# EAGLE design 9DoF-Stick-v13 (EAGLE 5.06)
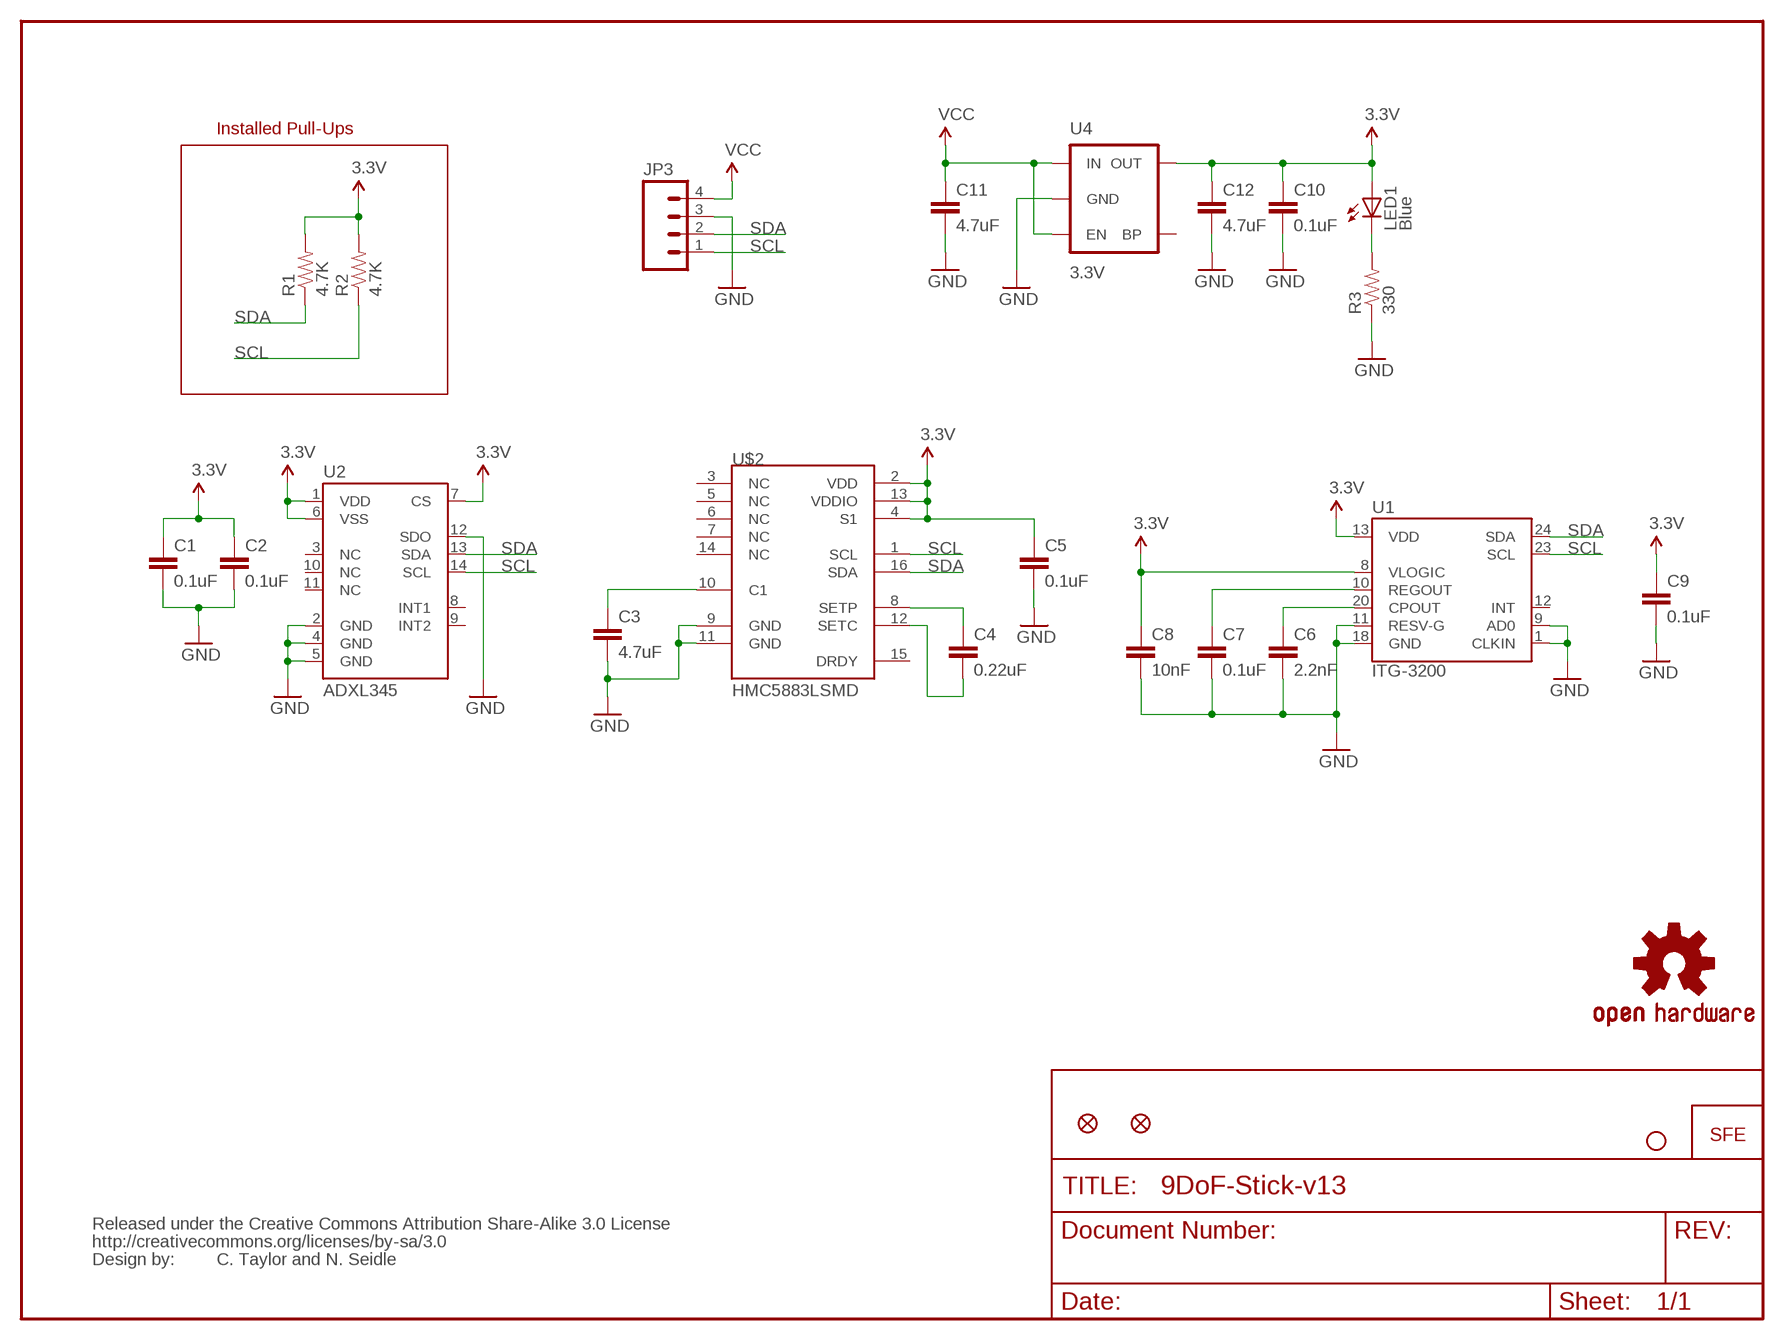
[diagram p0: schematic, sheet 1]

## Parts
C1  0.1uF  CAP0402-CAP  [0402-CAP]
C2  0.1uF  CAP0402-CAP  [0402-CAP]
C3  4.7uF  CAP0402-CAP  [0402-CAP]
C4  0.22uF  CAP0402-CAP  [0402-CAP]
C5  0.1uF  CAP0402-CAP  [0402-CAP]
C6  2.2nF  CAP0402-CAP  [0402-CAP]
C7  0.1uF  CAP0402-CAP  [0402-CAP]
C8  10nF  CAP0402-CAP  [0402-CAP]
C9  0.1uF  CAP0402-CAP  [0402-CAP]
C10  0.1uF  CAP0402-CAP  [0402-CAP]
C11  4.7uF  CAP0402-CAP  [0402-CAP]
C12  4.7uF  CAP0402-CAP  [0402-CAP]
JP1  FIDUCIAL1X2  [FIDUCIAL-1X2]
JP2  FIDUCIAL1X2  [FIDUCIAL-1X2]
JP3  M04PTH  [1X04]
JP4  LOGO-SFESK  [SFE-LOGO-FLAME]
JP5  STAND-OFF  [STAND-OFF]
LED1  Blue  LED0603  [LED-0603]
R1  4.7K  RESISTOR0402-RES  [0402-RES]
R2  4.7K  RESISTOR0402-RES  [0402-RES]
R3  330  RESISTOR0402-RES  [0402-RES]
U1  ITG-3200  [QFN-24]
U2  ADXL345  [LGA14]
U4  3.3V  V_REG_LDOSMD  [SOT23-5]
U$1  CREATIVE_COMMONS  [CREATIVE_COMMONS]
U$2  HMC5883LSMD  [16LPCC]
U$3  OSHW-LOGOS  [OSHW-LOGO-S]

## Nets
3.3V: C1.1 C2.1 C5.1 C8.1 C9.1 C10.1 C12.1 LED1.A R1.2 R2.2 U1.8(VLOGIC) U1.13(VDD) U2.1(VDD) U2.6(VSS) U2.7(CS) U4.5(OUT) U$2.2(VDD) U$2.4(S1) U$2.13(VDDIO)
GND: C1.2 C2.2 C3.2 C5.2 C6.2 C7.2 C8.2 C9.2 C10.2 C11.2 C12.2 JP3.3 R3.1 U1.1(CLKIN) U1.9(AD0) U1.11(RESV-G) U1.18(GND) U2.2(GND) U2.4(GND) U2.5(GND) U2.12(SDO) U4.2(GND) U$2.9(GND) U$2.11(GND)
N$1: C3.1 U$2.10(C1)
N$2: C4.1 U$2.8(SETP)
N$3: C4.2 U$2.12(SETC)
N$4: LED1.C R3.2
N$5: C6.1 U1.20(CPOUT)
N$7: C7.1 U1.10(REGOUT)
SCL: JP3.1 R2.1 U1.23(SCL) U2.14(SCL) U$2.1(SCL)
SDA: JP3.2 R1.1 U1.24(SDA) U2.13(SDA) U$2.16(SDA)
VCC: C11.1 JP3.4 U4.1(IN) U4.3(EN)
Unconnected: U1.12(INT) U2.3(NC) U2.8(INT1) U2.9(INT2) U2.10(NC) U2.11(NC) U4.4(BP) U$2.3(NC) U$2.5(NC) U$2.6(NC) U$2.7(NC) U$2.14(NC) U$2.15(DRDY)

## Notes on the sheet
- Installed Pull-Ups
- C. Taylor and N. Seidle

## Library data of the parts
C1-C12 = SparkFun:CAP: Capacitor
JP1 JP2 = SparkFun:FIDUCIAL: Fiducial Alignment Points
JP3 = SparkFun:M04: Header 4 Standard 4-pin 0.1" header. Use with straight break away headers (SKU : PRT-00116), right angle break away headers (PRT-00553), swiss pins (PRT-00743), machine pins (PRT-00117), and female headers (PRT-00115). Molex polarized connector foot print use with SKU : PRT-08231 with associated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
JP4 = SparkFun:LOGO-SFE: Spark Fun Electronics PCB Logo
JP5 = SparkFun:STAND-OFF: Stand Off
LED1 = SparkFun:LED: LEDs
R1-R3 = SparkFun:RESISTOR: Resistor
U1 = SparkFun:ITG-3200: ITG-3200 3-axis gyro, digital output, qfn24 package
U2 = SparkFun:ADXL345
U4 = SparkFun:V_REG_LDO: Voltage Regulator LDO Standard 150mA LDO voltage regulator in SOT-23 layout. Micrel part MIC5205. BP (by-pass) pin is used to lower output noise with 470pF cap.
U$1 = SparkFun:CREATIVE_COMMONS
U$2 = SparkFun:HMC5883L: 3 Axis Digital Compass IC
U$3 = SparkFun:OSHW-LOGO: Open Source Hardware Logo This logo indicates the piece of hardware it is found on incorporates a OSHW license and/or adheres to the definition of open source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

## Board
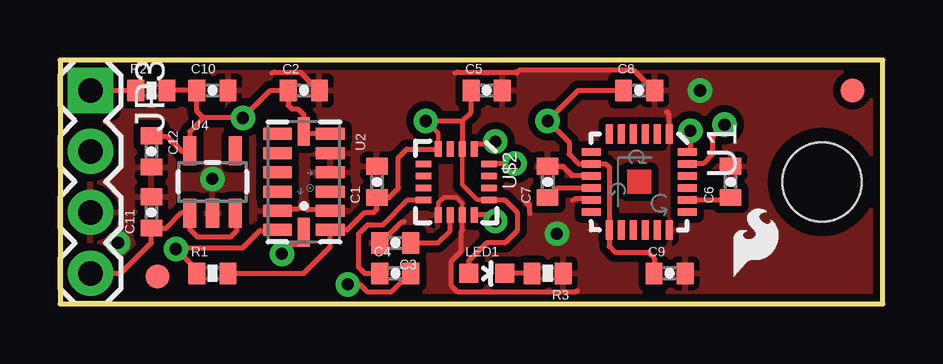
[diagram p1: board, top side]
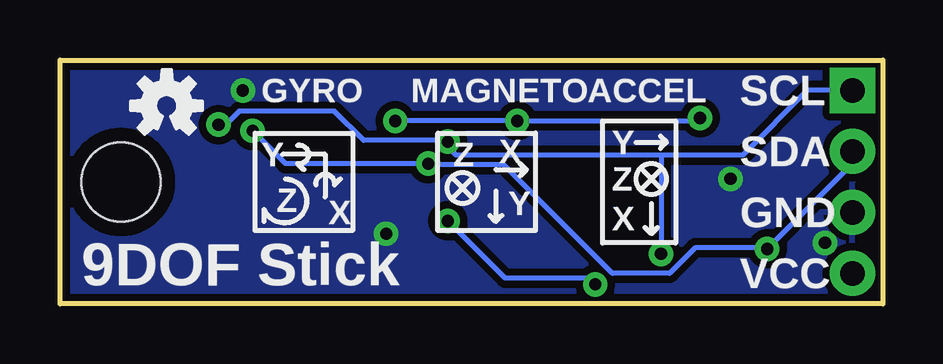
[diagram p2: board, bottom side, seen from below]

Size 34.29 x 10.16 mm. Coordinates in mm from the lower left corner, seen from the top.
Outline: 0,0 34.29,0 34.29,10.16 0,10.16 0,0
Copper layers (1*16): Top 0.035mm / dielectric 1.5mm / Bottom 0.035mm
Design rules "SparkFun *": minimum track width 7mil, minimum drill 20mil, track to track 8mil, track to pad 8mil, pad to pad 7mil, via to via 8mil, smd to smd 8mil, copper to edge 8mil, drill to drill 8mil, minimum pad ring 12mil, minimum via ring 10mil, stop-mask expansion 4mil, vias tented up to drill 20mil, thermal gap 10mil

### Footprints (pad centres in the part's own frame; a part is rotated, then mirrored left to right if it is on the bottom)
0402-CAP = smd 0.7 x 0.9: 1 -0.65,0; 2 0.65,0
FIDUCIAL-1X2 = smd 1 x 1: 1 0,0
1X04 = drill 1.016 pad 1.88 square: 1 0,0 | drill 1.016 pad 1.88 round: 2 2.54,0; 3 5.08,0; 4 7.62,0
STAND-OFF = hole 3.302: 0,0
LED-0603 = smd 0.8 x 0.8: A 0,-0.75; C 0,0.75
0402-RES = smd 0.7 x 0.9: 1 -0.65,0; 2 0.65,0
QFN-24 = smd 0.8 x 0.3: 1 -2,1.25; 2 -2,0.75; 3 -2,0.25; 4 -2,-0.25; 5 -2,-0.75; 6 -2,-1.25; 13 2,-1.25; 14 2,-0.75; 15 2,-0.25; 16 2,0.25; 17 2,0.75; 18 2,1.25 | smd 0.3 x 0.8: 7 -1.25,-2; 8 -0.75,-2; 9 -0.25,-2; 10 0.25,-2; 11 0.75,-2; 12 1.25,-2; 19 1.25,2; 20 0.75,2; 21 0.25,2; 22 -0.25,2; 23 -0.75,2; 24 -1.25,2
LGA14 = smd 0.5 x 1.2: 1 2,1.1; 2 1.2,1.1; 3 0.4,1.1; 4 -0.4,1.1; 5 -1.2,1.1; 6 -2,1.1; 8 -2,-1.1; 9 -1.2,-1.1; 10 -0.4,-1.1; 11 0.4,-1.1; 12 1.2,-1.1; 13 2,-1.1 | smd 1.2 x 0.5: 7 -2.1,0; 14 2.1,0
SOT23-5 = smd 0.55 x 1.2: 1 -0.95,-1.3; 2 0,-1.3; 3 0.95,-1.3; 4 0.95,1.3; 5 -0.95,1.3
16LPCC = smd 0.65 x 0.28: 1 -1.37,0.75; 2 -1.37,0.25; 3 -1.37,-0.25; 4 -1.37,-0.75; 9 1.37,-0.75; 10 1.37,-0.25; 11 1.37,0.25; 12 1.37,0.75 | smd 0.28 x 0.65: 5 -0.75,-1.37; 6 -0.25,-1.37; 7 0.25,-1.37; 8 0.75,-1.37; 13 0.75,1.37; 14 0.25,1.37; 15 -0.25,1.37; 16 -0.75,1.37

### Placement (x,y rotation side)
C1  13.21,5.08 90 top
C2  10.16,8.89 0 top
C3  13.97,2.54 180 top
C4  13.97,1.27 0 top
C5  17.78,8.89 0 top
C6  27.94,5.08 90 top
C7  20.32,5.08 90 top
C8  24.13,8.89 0 top
C9  25.4,1.27 0 top
C10  6.35,8.89 0 top
C11  3.81,3.81 90 top
C12  3.81,6.35 270 top
JP1  33.02,8.89 0 top
JP2  4.06,1.14 0 top
JP3  1.27,8.89 270 top
JP4  28.07,1.14 0 top
JP5  31.75,5.08 0 top
LED1  17.78,1.27 270 top
R1  6.35,1.27 0 top
R2  3.81,8.89 0 top
R3  20.32,1.27 180 top
U1  24.13,5.08 270 top
U2  10.16,5.08 270 top
U4  6.35,5.08 0 top
U$1  not placed on the board
U$2  16.51,5.08 270 top
U$3  29.84,8.26 0 bottom

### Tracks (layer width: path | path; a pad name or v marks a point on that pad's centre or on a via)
3.3V  (via drill 0.51)
  Top 0.178: U$2.4 15.76,7.1 v15.24,7.62 | U$2.2 16.76,4.96 17.39,4.33 U$2.13
  Top 0.203: C9.1 24.75,1.92 24.51,2.16 23.11,2.16 22.88,2.39 U1.13 22.88,5.7 22.75,5.83 U1.8 21.6,5.83 21.21,6.22 21.21,6.73 v20.32,7.62 21.59,8.89 C8.1 | 16.76,7.62 U$2.2 | 5.97,7.75 v7.62,7.75 8.76,8.89 C2.1 9.51,8.27 9.65,8.13 9.91,8.13 10.16,7.87 U2.7 10.21,7.11 11.23,7.11 U2.6 | 5.97,7.75 5.7,8.02 C10.1 R2.2 | 5.97,7.75 5.4,7.18 U4.5 5.11,6.38 5.08,6.35 4.47,6.96 3.81,6.96 C12.1 | v15.24,7.62 16.76,7.62 | LED1.A 17.03,1.79 17.78,2.54 18.54,2.54 19.05,3.05 19.05,3.81 18.53,4.33 U$2.13 | R1.2 10.16,1.27 11.26,2.37 U2.1 11.97,3.08 12.7,3.81 13.08,3.81 13.21,3.94 C1.1 13.7,4.43 14.1,4.83 14.1,6.1 14.45,6.45 U$2.4 | C5.1 17.13,7.99 16.76,7.62
  Bottom 0.203: v20.32,7.62 v15.24,7.62 7.75,7.62 v7.62,7.75
GND  (via drill 0.51)
  Top 0.178: U$2.9 15.76,4.2 16,4.45 16.51,4.45 16.76,4.2 U$2.11
  Top 0.203: 16.76,3.05 U$2.11 | 16.76,3.05 | U2.2 11.23,3.91 10.31,3.91 10.28,4.01 | 10.04,4.01 9.96,3.96 9.14,3.96 U2.12 | C3.2 13.36,2.54 14.22,3.4 14.34,3.42 | U1.11 22.1,4.37 21.44,4.37 21.35,4.3 | 19.58,3.76 19.56,3.86 19.56,4.17 19.44,4.18 | 16.76,3.05 16.71,3 16.71,2.18 16.31,1.78 16.31,0.76 16.56,0.51 21.49,0.51 21.57,0.53 | 16.46,9.63 16.56,9.65 18.95,9.65 19.03,9.63 19.1,9.7 19.15,9.75 23.88,9.75 24.69,8.94 C8.2 | C2.2 10.72,8.94 10.01,9.65 8.94,9.65 8.84,9.63 | U1.1 25.38,7.89 25.27,8 | U1.9 21.34,5.33 20.95,5.71 20.34,5.71 C7.2
  other vias: 26.67,8.89 20.7,2.92 6.35,5.21 2.41,2.54
  pour Bottom (isolate 0.305): 0,10.16 0,0 34.29,0 34.29,10.16
  pour Top (isolate 0.305): 0,10.16 0,0 34.29,0 34.29,10.16
N$1
  Top 0.203: U$2.10 16.26,3.05 15.75,2.54 C3.1
N$2
  Top 0.203: U$2.8 14.49,4.33 13.46,3.3 12.83,3.3 12.45,2.92 12.45,1.52 12.7,1.27 C4.1
N$3  (via drill 0.51)
  Top 0.203: v18.14,3.45 17.88,3.71 17.27,3.71 U$2.12 | v11.99,0.81 12.5,0.81 12.8,0.51 13.82,0.51 14.58,1.27 C4.2
  Bottom 0.203: v18.14,3.45 15.75,1.07 11.99,1.07 v11.99,0.81
N$4
  Top 0.203: R3.2 LED1.C
N$5
  Top 0.203: U1.20 27.84,4.33 C6.1
N$7
  Top 0.203: U1.10 20.72,4.83 C7.1
SCL  (via drill 0.51)
  Top 0.203: JP3.1 R2.1 | v18.14,6.76 18.14,6.66 17.32,6.66 17.27,6.6 17.27,6.45 U$2.1 | U1.23 26.16,5.84 26.8,5.84 27.18,6.22 27.18,6.96 v27.69,7.47 | v9.25,2.08 9.25,2.49 10.01,2.49 10.16,2.64 U2.14
  Bottom 0.203: 9.25,6.2 5.84,6.2 R2.1 JP3.1 | 9.25,6.2 17.78,6.2 18.14,6.55 v18.14,6.76 18.19,6.81 21.64,6.81 22.86,8.03 26.82,8.03 27.38,7.47 v27.69,7.47 | 9.25,6.2 v9.25,2.08
SDA  (via drill 0.51)
  Top 0.203: U2.13 9.04,3.05 8.33,3.05 7.62,2.34 4.88,2.34 v4.83,2.29 5.57,1.54 5.7,1.54 R1.1 | v18.95,5.84 17.88,5.84 U$2.16 | v26.26,7.21 26.26,6.4 26.16,6.3 U1.24
  Bottom 0.203: v26.26,7.21 24.89,5.84 v18.95,5.84 18.9,5.79 15.8,5.79 11.28,1.27 8.89,1.27 7.82,2.34 4.88,2.34 v4.83,2.29 1.27,5.84 JP3.2
VCC
  Top 0.203: JP3.4 2.54,1.27 3.81,2.54 C11.1 4.43,3.16 5.08,3.81 5.37,3.81 U4.1 5.4,3.11 5.71,2.79 7.11,2.79 7.37,3.05 7.37,3.71 U4.3

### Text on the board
tPlace: C. Taylor and N. Seidle
bPlace: SCL | ACCEL | MAGNETO | GYRO | SDA | Y | X | Z | Y | Z | Y | Z | GND | X | X | VCC | 9DOF Stick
